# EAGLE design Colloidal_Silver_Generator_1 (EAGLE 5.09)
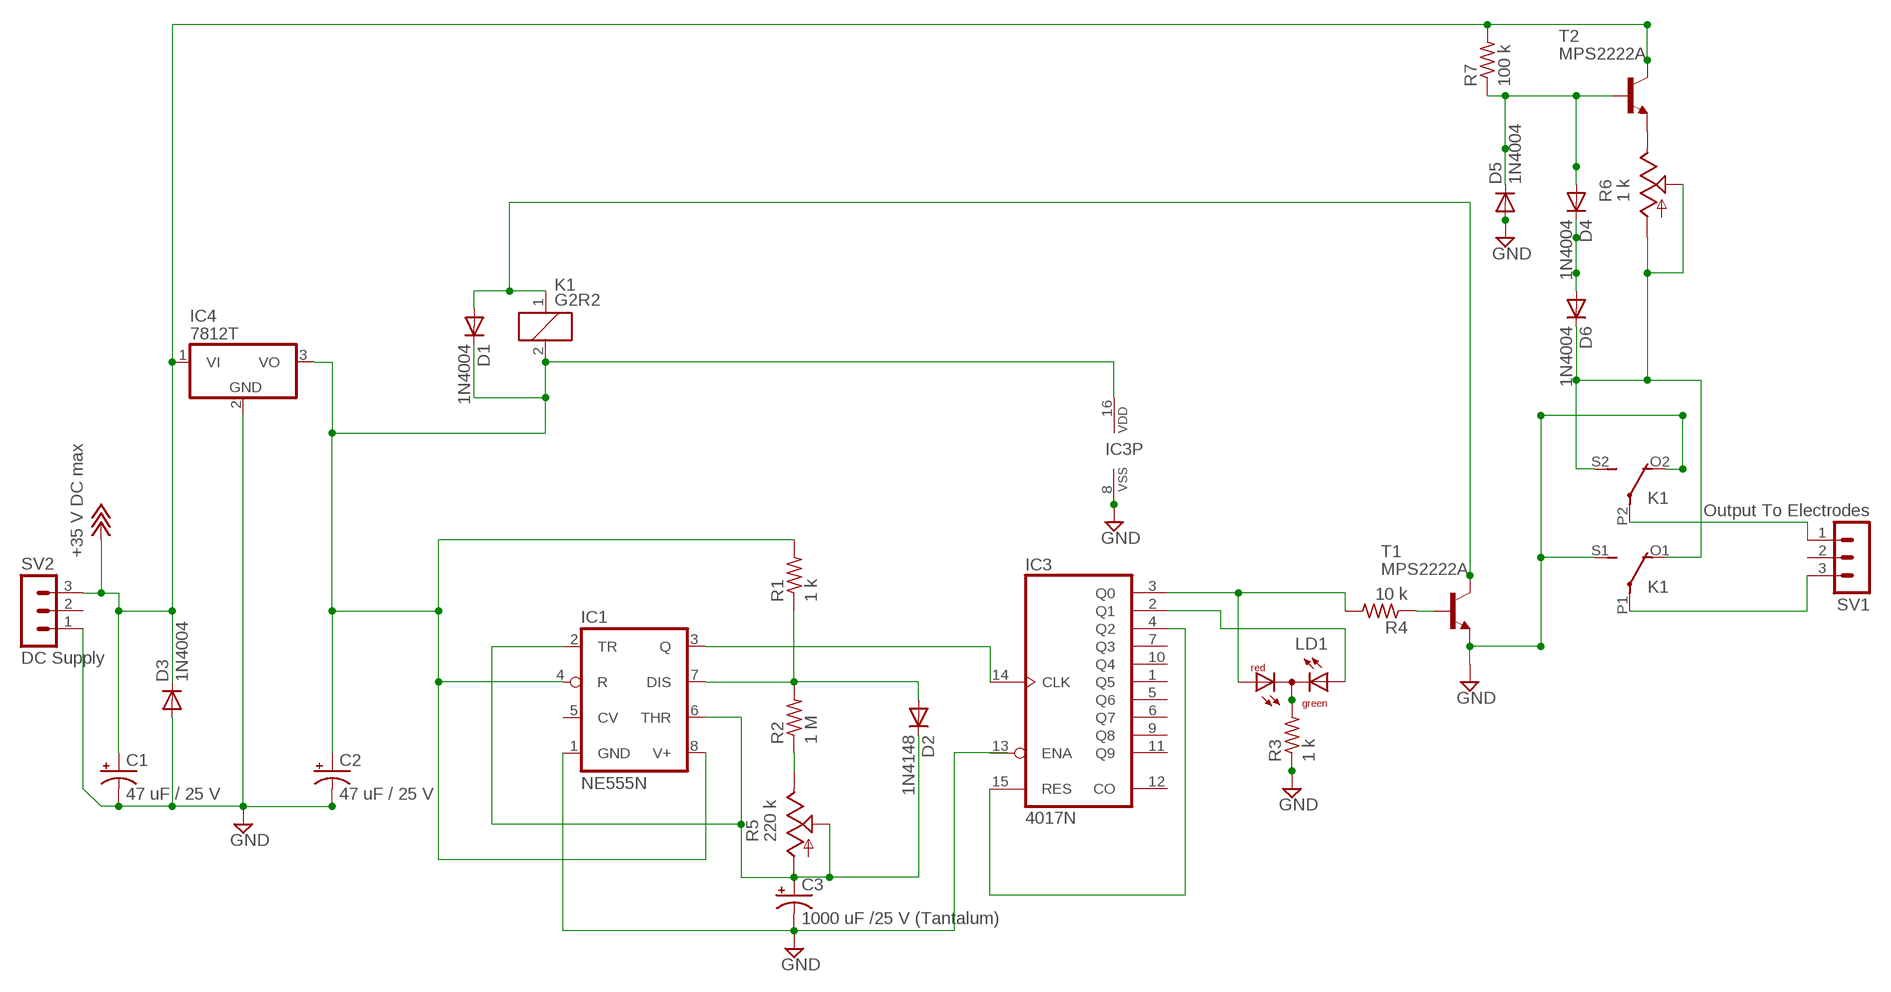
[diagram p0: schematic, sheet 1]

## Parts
C1  47 uF / 25 V  CPOL-USE5-8.5  [E5-8,5]
C2  47 uF / 25 V  CPOL-USE5-8.5  [E5-8,5]
C3  1000 uF /25 V (Tantalum)  CPOL-USE5-8.5  [E5-8,5]
D1  1N4004  [DO41-10]
D2  1N4148  1N4148DO35-10  [DO35-10]
D3  1N4004  [DO41-10]
D4  1N4004  [DO41-10]
D5  1N4004  [DO41-10]
D6  1N4004  [DO41-10]
IC1  NE555N  [DIL08]
IC3  4017N  [DIL16]
IC4  7812T  [TO220H]
K1  G2R2  [G2R2]
LD1  DUOLED-RG-C  [DUOLED-C-5MM]
R1  1 k  R-US_0309/12  [0309/12]
R2  1 M  R-US_0309/12  [0309/12]
R3  1 k  R-US_0309/12  [0309/12]
R4  10 k  R-US_0309/12  [0309/12]
R5  220 k  TRIM_US-B25U  [B25U]
R6  1 k  TRIM_US-B25U  [B25U]
R7  100 k  R-US_0309/12  [0309/12]
SV1  Output To Electrodes  MA03-1  [MA03-1]
SV2  DC Supply  MA03-1  [MA03-1]
T1  MPS2222A  MPS2222A-NPN-TO92-CBE  [TO92-CBE]
T2  MPS2222A  MPS2222A-NPN-TO92-CBE  [TO92-CBE]

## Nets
+18V: C1.+ D3.C IC4.1(VI) R7.2 SV2.3 T2.C ; supply symbol labelled +35 V DC max
GND: C1.- C2.- C3.- D3.A D5.A IC1.1(GND) IC3.8(VSS) IC4.2(GND) K1.O2(3:O) K1.S1(2:S) R3.1 SV2.1 T1.E
N$1: R2.1 R5.E
N$2: D2.A IC1.7(DIS) R1.1 R2.2
N$3: R6.E T2.E
N$4: D4.A D5.C R7.1 T2.B
N$5: D4.C D6.A
N$6: IC3.3(Q0) LD1.AR R4.2
N$7: D6.C K1.O1(2:O) K1.S2(3:S) R6.A R6.S
N$8: LD1.C R3.2
N$9: IC1.3(Q) IC3.14(CLK)
N$10: C2.+ D1.C IC1.4(R) IC1.8(V+) IC3.16(VDD) IC4.3(VO) K1.2 R1.2
N$11: IC3.2(Q1) LD1.AX(AG)
N$12: D1.A K1.1 T1.C
N$13: R4.1 T1.B
N$14: IC3.4(Q2) IC3.15(RES)
N$15: C3.+ D2.C IC1.2(TR) IC1.6(THR) R5.A R5.S
N$17: K1.P2(3:P) SV1.1
N$18: K1.P1(2:P) SV1.3
Unconnected: IC1.5(CV) IC3.1(Q5) IC3.5(Q6) IC3.6(Q7) IC3.7(Q3) IC3.9(Q8) IC3.10(Q4) IC3.11(Q9) IC3.12(CO) IC3.13(ENA) SV1.2 SV2.2

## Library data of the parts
C1-C3 = rcl:CPOL-US: POLARIZED CAPACITOR, American symbol
D1 D3-D6 = diode:1N4004: DIODE
D2 = diode:1N4148: DIODE
IC1 = linear:*555: TIMER
IC3 = 40xx:4017: COUNTER/DIVIDER
IC4 = linear:78*: Positive VOLTAGE REGULATOR Source: http://cache.national.com/ds/LM/LM78L05.pdf http://www.fairchildsemi.com/ds/LM/LM7805.pdf
K1 = relay:G2R2: RELAY 2 x switch, Omron
LD1 = led:DUOLED-RG-C: DUO LED 2 colors (red/green), 5 mm, round, common Cathode www.ligitek.com or other producers.
R1-R4 R7 = rcl:R-US_: RESISTOR, American symbol
R5 R6 = pot:TRIM_US-: POTENTIOMETER
SV1 SV2 = con-lstb:MA03-1: PIN HEADER
T1 T2 = transistor:*-NPN-: NPN Transistror BF959 corrected 2008.03.06

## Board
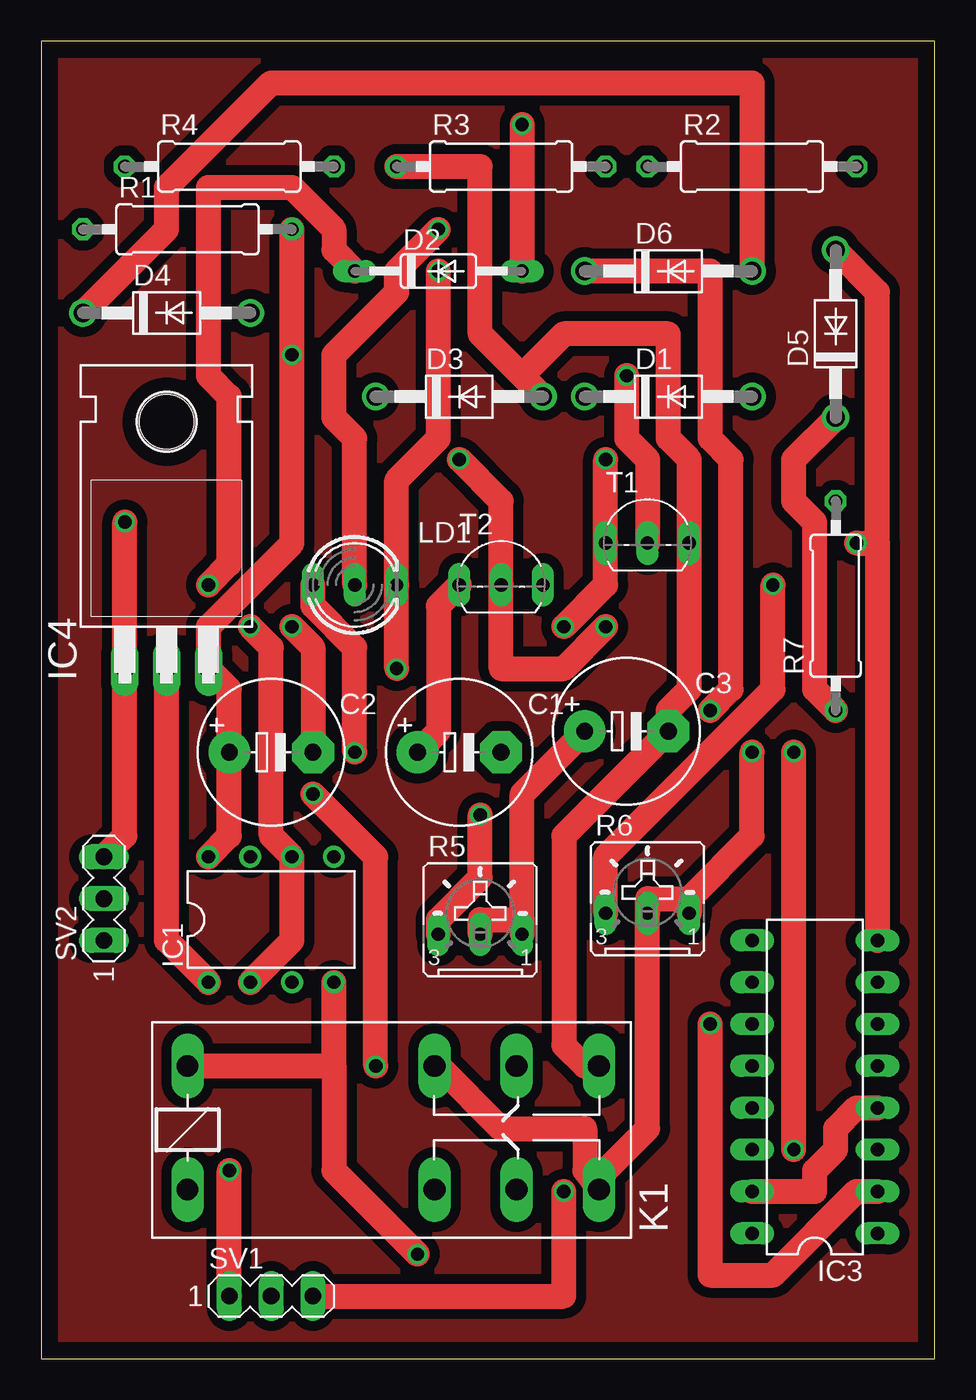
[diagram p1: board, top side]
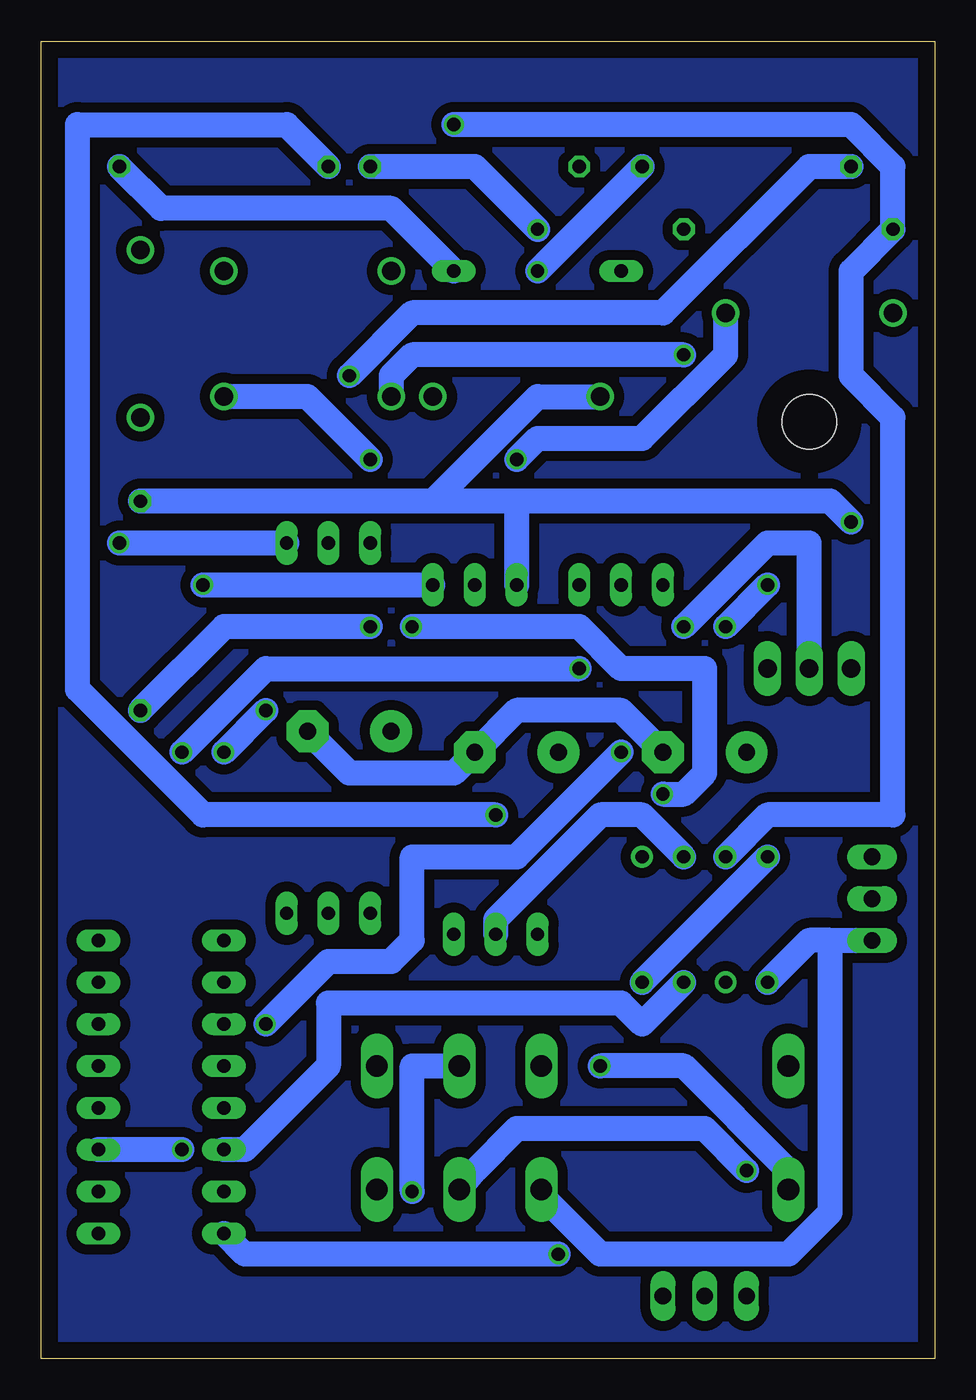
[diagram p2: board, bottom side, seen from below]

Size 54.28 x 80 mm. Coordinates in mm from the lower left corner, seen from the top.
Outline: 0,0 54.28,0 54.28,80 0,80 0,0
Copper layers (1*16): Top 0.035mm / dielectric 1.5mm / Bottom 0.035mm
Design rules "default *": minimum track width 60mil, minimum drill 32mil, track to track 8mil, track to pad 8mil, pad to pad 8mil, via to via 8mil, smd to smd 8mil, copper to edge 40mil, drill to drill 8mil, minimum pad ring 10mil, minimum via ring 8mil, stop-mask expansion 4mil, vias tented up to drill 0mil, thermal gap 10mil

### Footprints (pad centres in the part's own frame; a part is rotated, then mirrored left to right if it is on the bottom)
E5-8,5 = drill 1.016 pad 2.54 round: + -2.54,0 | drill 1.016 pad 2.54 octagon: - 2.54,0
DO41-10 = drill 1.118 round: A 5.08,0; C -5.08,0
DO35-10 = drill 0.813 long: A 5.08,0; C -5.08,0
DIL08 = drill 0.813 pad 1.27 round: 1 -3.81,-3.81; 2 -1.27,-3.81; 3 1.27,-3.81; 4 3.81,-3.81; 5 3.81,3.81; 6 1.27,3.81; 7 -1.27,3.81; 8 -3.81,3.81
DIL16 = drill 0.813 long: 1 -8.89,-3.81; 2 -6.35,-3.81; 3 -3.81,-3.81; 4 -1.27,-3.81; 5 1.27,-3.81; 6 3.81,-3.81; 7 6.35,-3.81; 8 8.89,-3.81; 9 8.89,3.81; 10 6.35,3.81; 11 3.81,3.81; 12 1.27,3.81; 13 -1.27,3.81; 14 -3.81,3.81; 15 -6.35,3.81; 16 -8.89,3.81
TO220H = drill 1.118 long: 1 -2.54,-10.16; 2 0,-10.16; 3 2.54,-10.16 | hole 3.302: 0,4.826
G2R2 = drill 1.321 long: 1 -2.54,-3.683; 2 -2.54,3.81; O1 12.471,3.81; O2 12.471,-3.683; P1 17.45,3.81; P2 17.45,-3.683; S1 22.454,3.81; S2 22.454,-3.683
DUOLED-C-5MM = drill 0.813 long: AR 2.54,0; AX -2.54,0; C 0,0
0309/12 = drill 0.813 octagon: 1 -6.35,0; 2 6.35,0
B25U = drill 0.813 long: A 2.54,-0.889; E -2.54,-0.889; S 0,-0.889
MA03-1 = drill 1.016 long: 1 -2.54,0; 2 0,0; 3 2.54,0
TO92-CBE = drill 0.813 long: B 0,0; C -2.54,0; E 2.54,0

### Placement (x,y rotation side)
C1  25.4,36.83 0 top
C2  13.97,36.83 0 top
C3  35.56,38.1 0 top
D1  38.1,58.42 0 top
D2  24.13,66.04 0 top
D3  25.4,58.42 0 top
D4  7.62,63.5 0 top
D5  48.26,62.23 90 top
D6  38.1,66.04 0 top
IC1  13.97,26.67 0 top
IC3  46.99,16.51 90 top
IC4  7.62,52.07 0 top
K1  11.43,13.97 0 top
LD1  19.05,46.99 0 top
R1  8.89,68.58 0 top
R2  43.18,72.39 0 top
R3  27.94,72.39 0 top
R4  11.43,72.39 0 top
R5  26.67,26.67 0 top
R6  36.83,27.94 0 top
R7  48.26,45.72 90 top
SV1  13.97,3.81 0 top
SV2  3.81,27.94 90 top
T1  36.83,49.53 0 top
T2  27.94,46.99 0 top

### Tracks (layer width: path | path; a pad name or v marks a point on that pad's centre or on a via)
+18V  (via drill 0.81)
  Top 1.524: T2.C 24.13,45.72 24.13,38.1 C1.+ | SV2.3 5.08,31.75 IC4.1 v5.08,50.8
  Bottom 1.524: 30.48,52.07 R7.2 | 30.48,52.07 24.13,58.42 D3.C | v5.08,50.8 6.35,52.07 25.4,52.07 | 25.4,52.07 30.48,52.07 | 25.4,52.07 T2.C
GND  (via drill 0.81)
  Top 1.524: IC4.2 7.62,25.4 IC1.1 | 50.8,49.53 50.8,64.77 D5.A | 50.8,49.53 IC3.8 | R3.1 26.67,72.39 26.67,62.23 29.21,59.69 | 29.21,59.69 D3.A | K1.S1 33.02,17.78 31.75,19.05 31.75,31.75 C3.- 38.1,39.37 39.37,40.64 T1.E 39.37,54.61 38.1,55.88 38.1,62.23 31.75,62.23 29.21,59.69 | v49.53,49.53 50.8,49.53 | v15.24,44.45 16.51,43.18 C2.-
  Bottom 1.524: IC1.1 7.62,25.4 6.35,25.4 | 6.35,25.4 SV2.1 | 6.35,25.4 6.35,8.89 8.89,6.35 20.32,6.35 24.13,10.16 K1.O2 | C2.- 19.05,39.37 25.4,39.37 C1.- 29.21,35.56 35.56,35.56 C3.- | T1.E v49.53,49.53 | IC4.2 7.62,49.53 10.16,49.53 v15.24,44.45
N$1  (via drill 0.81)
  Top 1.524: v26.67,33.02 26.67,29.21 24.13,26.67 R5.E
  Bottom 1.524: v26.67,33.02 44.45,33.02 52.07,40.64 52.07,74.93 39.37,74.93 R2.1
N$2  (via drill 0.81)
  Top 1.524: v29.21,74.93 D2.A
  Bottom 1.524: D2.A 33.02,69.85 46.99,69.85 R2.2 | IC1.7 10.16,33.02 2.54,33.02 2.54,57.15 5.08,59.69 5.08,66.04 R1.1 2.54,72.39 5.08,74.93 v29.21,74.93
N$3  (via drill 0.81)
  Top 1.524: v44.45,46.99 44.45,40.64 34.29,30.48 R6.E
  Bottom 1.524: v44.45,46.99 T2.E
N$4  (via drill 0.81)
  Top 1.524: R7.1 46.99,40.64 46.99,50.8 45.72,52.07 45.72,54.61 D5.C | v25.4,54.61 27.94,52.07 T2.B 27.94,41.91 31.75,41.91 v34.29,44.45
  Bottom 1.524: v25.4,54.61 24.13,55.88 17.78,55.88 12.7,60.96 D4.A | R7.1 43.18,44.45 v34.29,44.45
N$5
  Top 1.524: D4.C 7.62,68.58 7.62,71.12 13.97,77.47 43.18,77.47 D6.A
N$6  (via drill 0.81)
  Top 1.524: v45.72,12.7 v45.72,36.83 | v21.59,41.91 LD1.AR 21.59,53.34 24.13,55.88 v24.13,66.04
  Bottom 1.524: v45.72,12.7 IC3.3 | v45.72,36.83 40.64,41.91 v21.59,41.91 | v24.13,66.04 R4.2
N$7  (via drill 0.81)
  Top 1.524: 39.37,27.94 36.83,27.94 R6.S 36.83,13.97 34.29,11.43 K1.S2 33.02,11.43 33.02,13.97 27.94,13.97 24.13,17.78 K1.O1 | D6.C 40.64,66.04 40.64,55.88 41.91,54.61 41.91,40.64 v40.64,39.37 | v43.18,36.83 43.18,31.75 39.37,27.94 | 39.37,27.94 R6.A
  Bottom 1.524: v43.18,36.83 v40.64,39.37
N$8  (via drill 0.81)
  Top 1.524: LD1.C 19.05,55.88 17.78,57.15 17.78,60.96 21.59,64.77 21.59,66.04 v24.13,68.58
  Bottom 1.524: v24.13,68.58 27.94,72.39 R3.2
N$9
  Bottom 1.524: IC3.14 41.91,12.7 36.83,17.78 36.83,21.59 19.05,21.59 17.78,20.32 IC1.3
N$10  (via drill 0.81)
  Top 1.524: R1.2 v15.24,60.96 15.24,49.53 10.16,44.45 IC4.3 11.43,40.64 C2.+ 11.43,31.75 IC1.8 | v22.86,6.35 17.78,11.43 17.78,17.78 | 17.78,17.78 IC1.4 | K1.2 17.78,17.78
  Bottom 1.524: D1.C 33.02,59.69 31.75,60.96 v15.24,60.96 | IC1.4 IC1.8 | IC3.16 41.91,6.35 v22.86,6.35
N$11  (via drill 0.81)
  Top 1.524: IC3.2 49.53,10.16 44.45,5.08 40.64,5.08 v40.64,20.32 | v19.05,36.83 19.05,43.18 16.51,45.72 LD1.AX
  Bottom 1.524: v40.64,20.32 36.83,24.13 33.02,24.13 31.75,25.4 31.75,30.48 25.4,30.48 v19.05,36.83
N$12  (via drill 0.81)
  Top 1.524: v34.29,54.61 T1.C 34.29,46.99 v31.75,44.45 | v20.32,17.78 20.32,30.48 v16.51,34.29
  Bottom 1.524: v34.29,54.61 38.1,58.42 D1.A | v20.32,17.78 15.24,17.78 8.89,11.43 K1.1 | v16.51,34.29 15.24,34.29 13.97,35.56 13.97,41.91 19.05,41.91 21.59,44.45 v31.75,44.45
N$13  (via drill 0.81)
  Top 1.524: T1.B 36.83,54.61 35.56,55.88 v35.56,59.69
  Bottom 1.524: v35.56,59.69 31.75,63.5 16.51,63.5 7.62,72.39 R4.1
N$14
  Top 1.524: IC3.15 46.99,10.16 46.99,11.43 48.26,12.7 48.26,13.97 49.53,15.24 IC3.4
N$15  (via drill 0.81)
  Top 1.524: 29.21,26.67 26.67,26.67 R5.S | 29.21,26.67 29.21,34.29 C3.+ | 29.21,26.67 R5.A | IC1.2 15.24,25.4 IC1.6 13.97,31.75 13.97,43.18 v12.7,44.45 | D2.C 17.78,67.31 17.78,68.58 15.24,71.12 10.16,71.12 10.16,59.69 11.43,58.42 11.43,48.26 v10.16,46.99
  Bottom 1.524: v12.7,44.45 v10.16,46.99 | IC1.6 17.78,33.02 20.32,33.02 26.67,26.67 R5.S
N$16
  pour Top (isolate 0.61): 0,80.01 54.61,80.01 54.61,0 0,0
N$17  (via drill 0.81)
  Top 1.524: SV1.1 v11.43,11.43
  Bottom 1.524: v11.43,11.43 13.97,13.97 25.4,13.97 27.94,11.43 K1.P2
N$18  (via drill 0.81)
  Top 1.524: SV1.3 31.75,3.81 v31.75,10.16
  Bottom 1.524: v31.75,10.16 31.75,17.78 K1.P1
N$19
  pour Bottom (isolate 0.61): 0,80.01 54.61,80.01 54.61,0 0,0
